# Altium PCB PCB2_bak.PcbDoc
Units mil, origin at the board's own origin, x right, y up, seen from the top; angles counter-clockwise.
Board outline 600 x 1690 mil, 2 copper layers (Top Layer, Bottom Layer), stack 61.756 mil thick; 62 components, 59 nets, 262 pads, 74 vias.
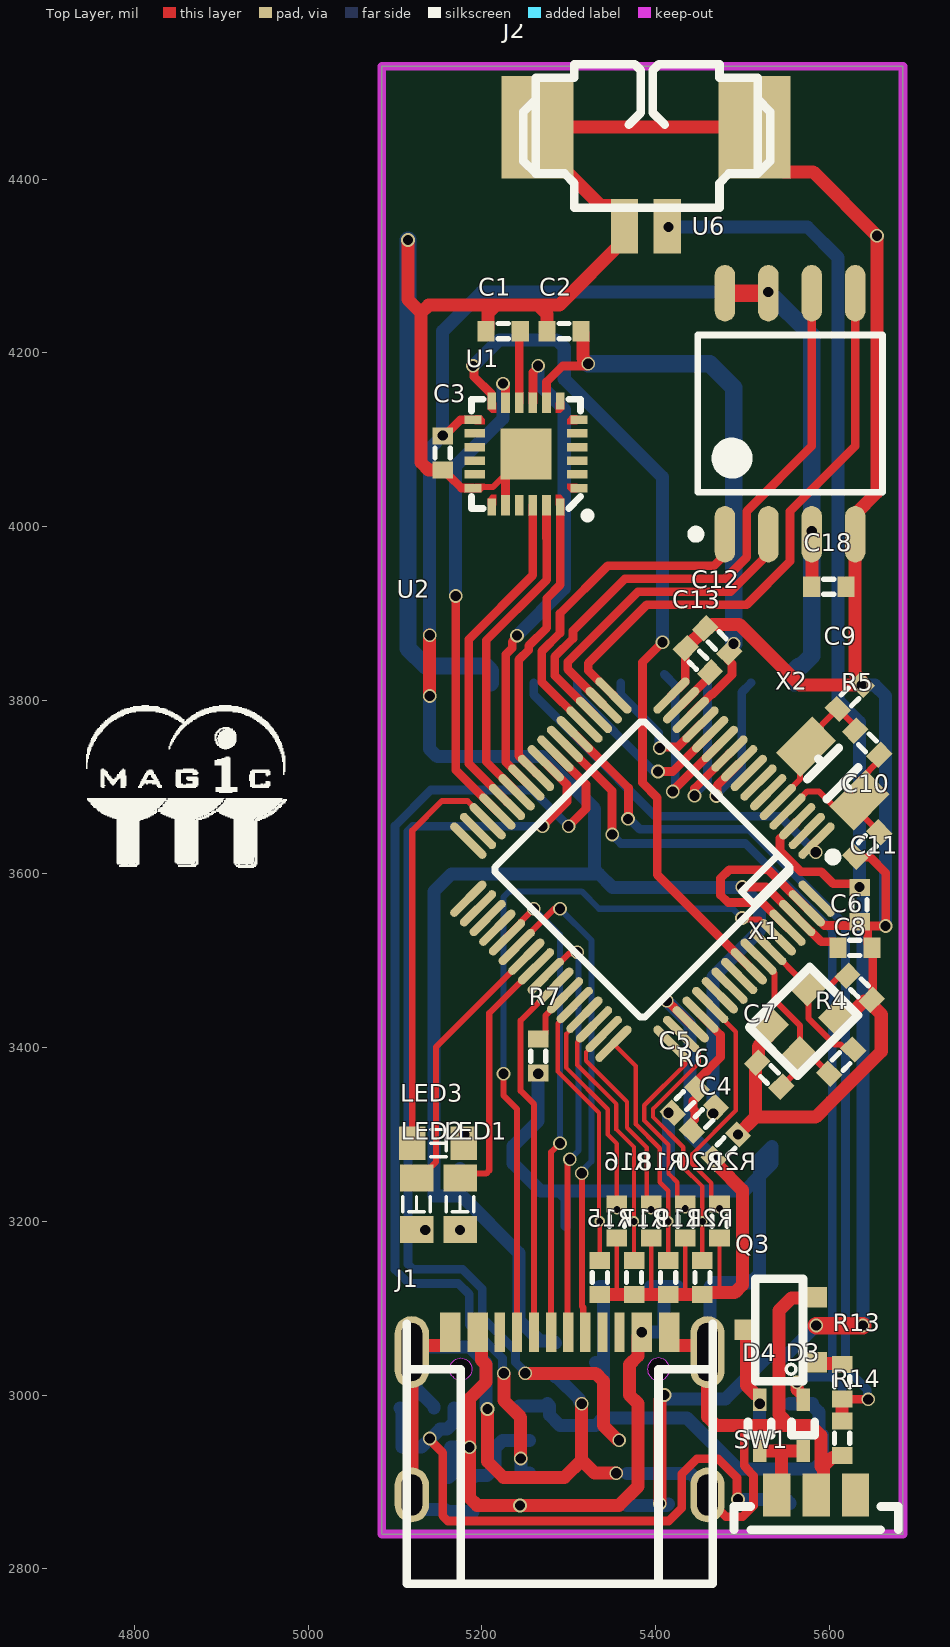
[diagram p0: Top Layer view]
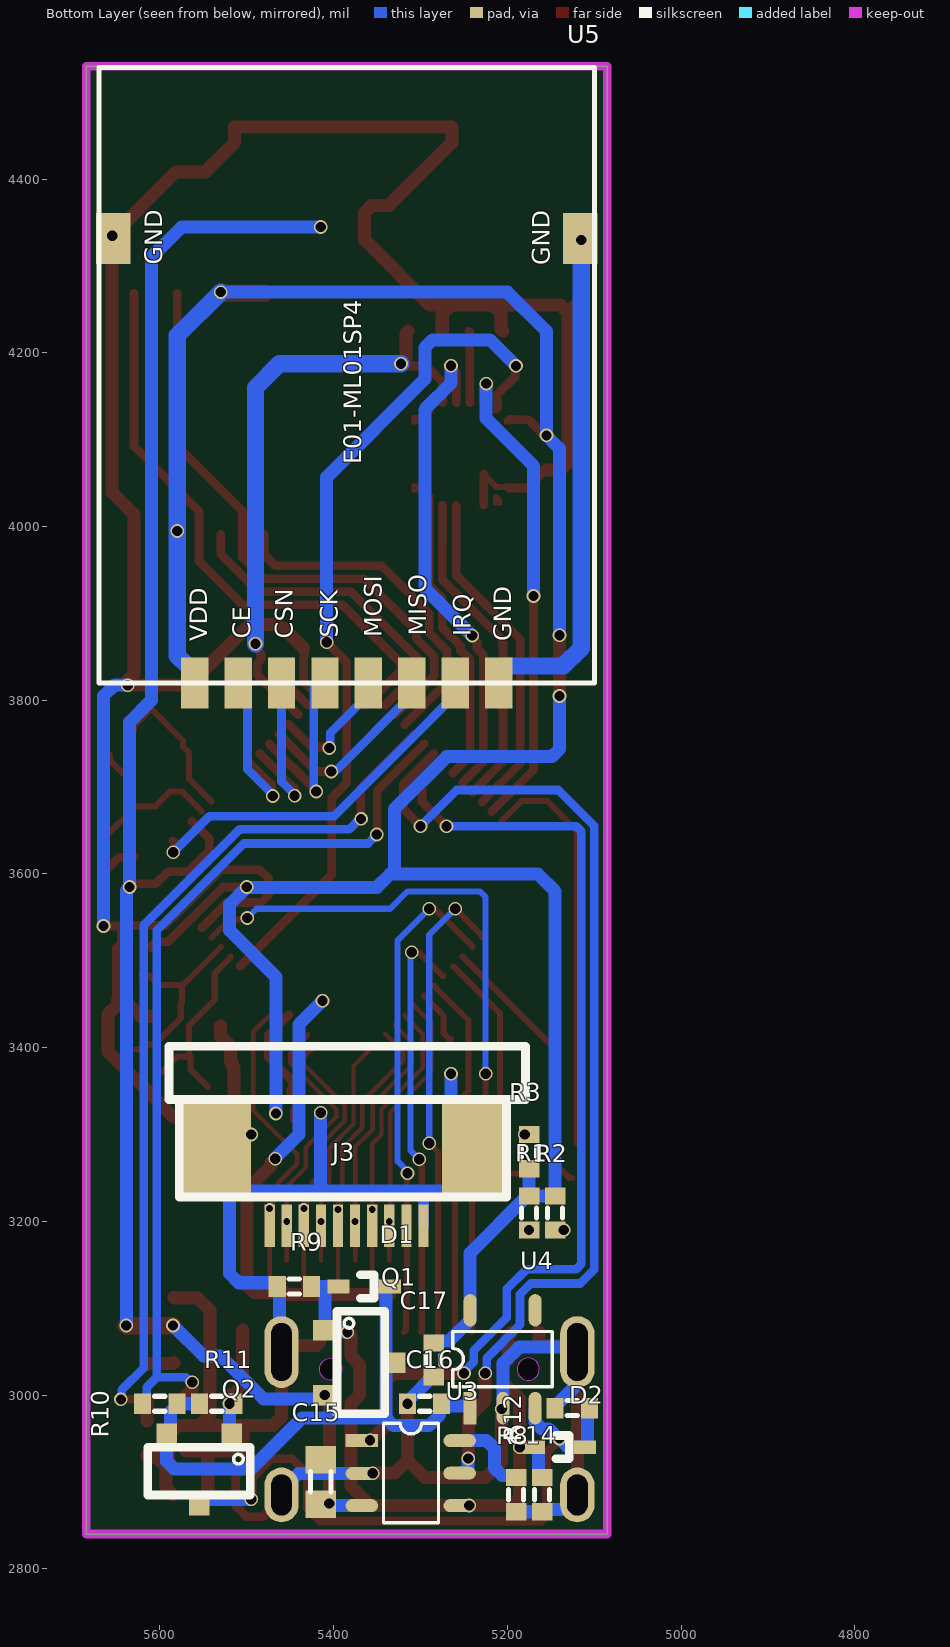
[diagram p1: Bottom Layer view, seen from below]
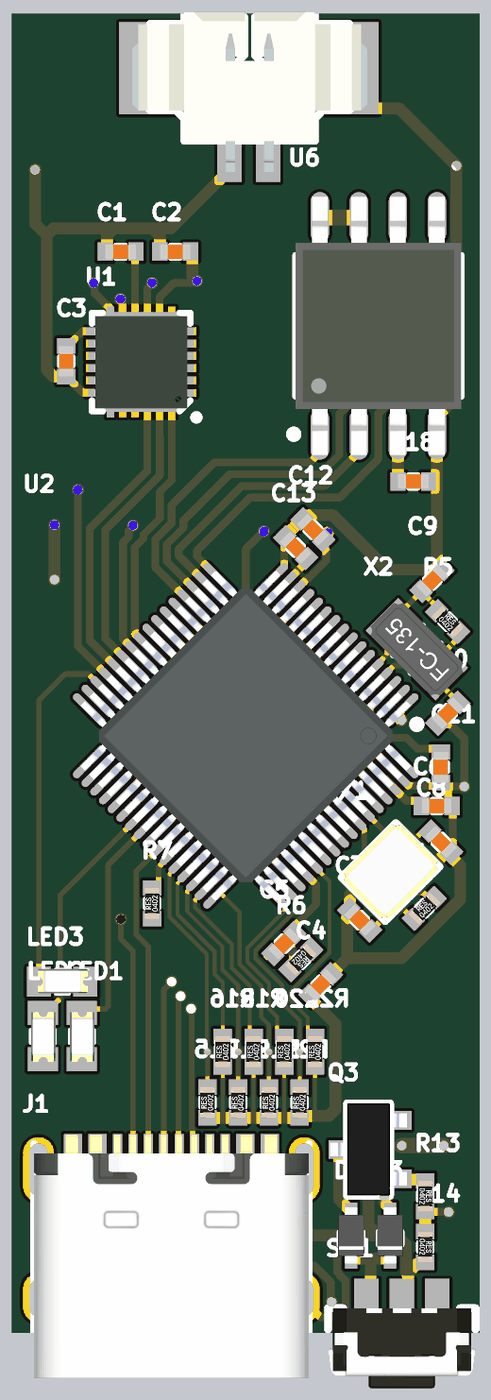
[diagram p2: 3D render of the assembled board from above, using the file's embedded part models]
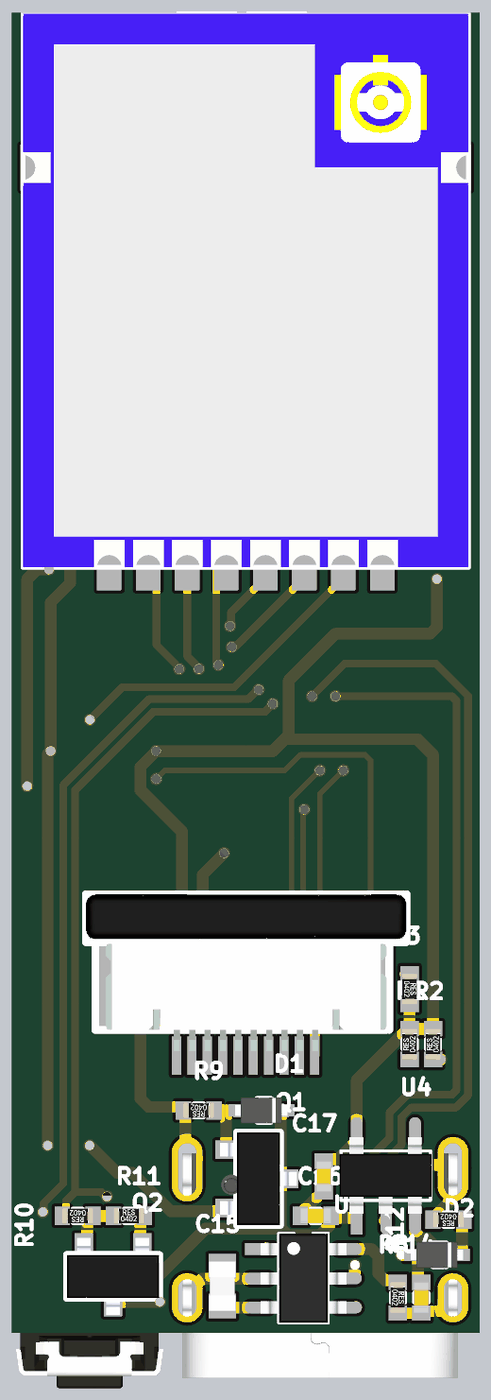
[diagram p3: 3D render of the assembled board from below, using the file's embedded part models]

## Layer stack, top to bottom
Top Solder: solder mask 1, SM-001, Dk 4
Top Layer: signal copper 1.378
Dielectric 1: core 59, Core-043, Dk 4.3
Bottom Layer: signal copper 1.378
Bottom Solder: solder mask 1, SM-001, Dk 4

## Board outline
5085,2840 5085,4530 5685,4530 5685,2840

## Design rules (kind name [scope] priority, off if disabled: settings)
Clearance [All] p1: gap=5 ignorepadtopadclearanceinfootprint=FALSE
PolygonConnect [All] p1: connectstyle=Relief reliefconductorwidth=10 reliefentries=4 polygonreliefangle="90 Angle" airgapwidth=10
RoutingVias [All] p1: holewidth=28 width=50 viastyle="Through Hole" minholewidth=7.87 minwidth=11.81 maxholewidth=28 maxwidth=50
SolderMaskExpansion [All] p1: expansion=4 istentingtop=FALSE
Width [All] p1: maxlimit=40 minlimit=4 preferedwidth=10 minimp=50.000000 maximp=50.000000 favimp=50.000000
30 further rules are at their usual default settings.

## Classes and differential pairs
net class ADC[0..7]: ADC0 ADC1 ADC2 ADC3 ADC4 ADC5 ADC6 ADC7
component class U_W25Q128: C18 U6
component class U_Pressure: J3 R15 R16 R17 R18 R19 R20 R21 R22
component class U_Power: C14 C15 C16 C17 D1 D2 D3 D4 Q1 Q2 Q3 R8 R9 R10 R11 R12 R13 R14 SW1 U3 U4
component class U_NRF24L01_PA_LNA: U5
component class U_NANO103: C4 C5 C6 C7 C8 C9 C10 C11 C12 C13 R4 R5 R6 R7 U2 X1 X2
component class U_ICM_20948: C1 C2 C3 U1
component class Sheet1: J1 J2 LED1 LED2 LED3 R1 R2 R3

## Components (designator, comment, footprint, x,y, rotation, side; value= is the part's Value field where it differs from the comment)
C1 "Cap" CAP_0402 5244.37,4225 r180 top value=0.1uf
C2 "Cap" CAP_0402 5314.37,4225 r180 top value=0.1uf
C3 "Cap" CAP_0402 5155,4104.37 r270 top value=0.1uf
C4 "Cap" CAP_0402 5495,3300 r225 top value=0.1uF
C5 "Cap" CAP_0402 5420,3325 r45 top value=0.1uF
C6 "Cap" CAP_0402 5649.37,3515 r180 top value=0.1uF
C7 "Cap" CAP_0402 5545,3355 r135 top value=22pF
C8 "Cap" CAP_0402 5621.09,3482.84 r315 top value=22pF
C9 "Cap" CAP_0402 5610,3790 r45 top value=22pF
C10 "Cap" CAP_0402 5657.84,3647.84 r225 top value=22pF
C11 "Cap" CAP_0402 5635,3545 r90 top value=0.1uF
C12 "Cap" CAP_0402 5457.16,3882.84 r315 top value=0.1uF
C13 "Cap" CAP_0402 5435,3860 r315 top value=0.1uF
C14 "Cap" CAP_0402 5160,2905 r270 bottom value=1uF
C15 "Cap" Cap_0603 5415,2900 r90 bottom value=10uF
C16 "Cap" CAP_0402 5275.63,2990 r0 bottom value=1uF
C17 "Cap" CAP_0402 5285,3060 r270 bottom value=1uF
C18 "Cap" CAP_0402 5580,3930.71 r0 top value=0.1uF
D1 "B5819WT" SOD-523 5365,3125 r180 bottom
D2 "B5819WT" SOD-523 5140,2940 r180 bottom
D3 "B5819WT" SOD-523 5570,2965 r270 top
D4 "B5819WT" SOD-523 5520,2965 r270 top
J1 "USB TYPE C" USBC-SMD16F 5119.45,2885 r0 top
J2 "Plug2" Terminal_block_2pin_1.25mm_SMD 5390,4460 r0 top
J3 "Plug10" FPC0.5-10PS 5296.57,3195 r0 bottom
LED1 "LED" SMD-0603_LED 5175,3190.55 r90 top
LED2 "LED" SMD-0603_LED 5125,3190.55 r90 top
LED3 "LED" SMD-0603_LED 5179.45,3290 r180 top
Q1 "SI2301DS-T1" SOT-23 5331.26,3037.4 r270 bottom
Q2 "SI2301DS-T1" SOT-23 5555,2875 r0 bottom
Q3 "MMS9013L-TP" SOT-23 5505,3075 r90 top
R1 "Res" RES_0402 5175,3190 r90 bottom value=1K
R2 "Res" RES_0402 5145,3190 r90 bottom value=1K
R3 "Res" RES_0402 5175,3300 r270 bottom value=1K
R4 "Res" RES_0402 5600,3370 r45 top value=1M
R5 "Res" RES_0402 5630,3765 r315 top value=1M
R6 "Res" RES_0402 5469.69,3332.12 r225 top value=0
R7 "Res" RES_0402 5265,3370.63 r90 top value=0
R8 "Res" RES_0402 5190,2905 r270 bottom value=2.2K
R9 "Res" RES_0402 5425.63,3125 r0 bottom value=100K
R10 "Res" RES_0402 5580.63,2990 r0 bottom value=10K
R11 "Res" RES_0402 5554.37,2990 r180 bottom value=100K
R12 "Res" RES_0402 5105.63,2985 r0 bottom value=100K
R13 "Res" RES_0402 5615,3035 r270 top value=2.2K
R14 "Res" RES_0402 5615,2970 r270 top value=10K
R15 "Res" RES_0402 5335.94,3115.63 r90 top value=10K
R16 "Res" RES_0402 5355.63,3180.63 r90 top value=10K
R17 "Res" RES_0402 5375.31,3115.63 r90 top value=10K
R18 "Res" RES_0402 5395,3180.63 r90 top value=10K
R19 "Res" RES_0402 5414.68,3115.63 r90 top value=10K
R20 "Res" RES_0402 5434.37,3180.63 r90 top value=10K
R21 "Res" RES_0402 5454.05,3115.63 r90 top value=10K
R22 "Res" RES_0402 5473.74,3180.63 r90 top value=10K
SW1 "SPST" ST01-111 5630.28,2885 r180 top
U1 "ICM-20948" QFN_24_3X3 5250.94,4083.62 r180 top
U2 "NANO103SD3AE" MCU_LQFP_64_7x7 5385,3605 r225 top
U3 "TP4059" SOT23-6 5342.68,2967.52 r180 bottom
U4 "AP2112K-3.3TRG1" SOT23-5 5262.87,3009.8 r90 bottom
U5 "NRF24L01" NRF24L01P+PA+LNA+IPX 5670.43,4528.66 r180 bottom
U6 "Flash" "8-Pin SOIC 208-mil" 5555,4130 r90 top
X1 "Xtal" 2520S 5610.93,3435.93 r225 top value=12MHz
X2 "Xtal" FC-135 5660.33,3754.32 r135 top value=32.768KHz

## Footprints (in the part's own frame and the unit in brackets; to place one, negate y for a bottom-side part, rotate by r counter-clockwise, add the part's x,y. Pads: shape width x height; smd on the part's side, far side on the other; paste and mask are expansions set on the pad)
"8-Pin SOIC 208-mil" [mm]
  oval 1.65x0.6 smd: 1(-3.525,1.905) 2(-3.525,0.635) 3(-3.525,-0.635) 4(-3.525,-1.905) 5(3.525,-1.905) 6(3.525,-0.635) 7(3.525,0.635) 8(3.525,1.905)
  silkscreen extent -3.65,-2.7 2.3,2.88, body extent -4.2,-2.69 4.2,2.69, height 2.3
2520S [mm]
  rect 0.9x0.8 smd: 1(0,-1.25) 2(1.65,0) ""(0,0) ""(1.65,-1.25)
  silkscreen extent -0.43,-1.63 2.07,0.37, body extent -0.49,-1.69 2.11,0.41, height 0.55
CAP_0402 [mm]
  rect 0.5x0.6 smd: 1(0,0) 2(1,0)
  silkscreen extent 0.35,-0.22 0.65,0.22, body extent 0,-0.25 1,0.25, height 0.48
Cap_0603 [mm]
  rect 0.8x0.9 smd: 1(-0.65,0) 2(0.65,0)
  silkscreen extent -0.3,-0.3 0.3,0.3, body extent -0.8,-0.43 0.8,0.43, height 0.83
FC-135 [mm]
  rect 1x1.5 smd: 1(-0.79,1.7) 2(1.42,1.7)
  silkscreen extent -0.29,1.05 0.92,2.35, body extent -1.28,0.95 1.92,2.45, height 0.8
FPC0.5-10PS [mm]
  rect 0.3x1.25 smd: 1(0,0) 2(0.5,0) 3(1,0) 4(1.5,0) 5(2,0) 6(2.5,0) 7(3,0) 8(3.5,0) 9(4,0) 10(4.5,0)
  rect 2x3 smd: ""(-1.54,-2.325) ""(6.04,-2.32)
  silkscreen extent -2.99,-5.25 7.44,-0.84, body extent -2.99,-5.25 7.44,-0.14, height 2.03
MCU_LQFP_64_7x7 [mm]
  oval 1.4x0.25 smd: 1(-4.2,3) 2(-4.2,2.6) 3(-4.2,2.2) 4(-4.2,1.8) 5(-4.2,1.4) 6(-4.2,1) 7(-4.2,0.6) 8(-4.2,0.2) 9(-4.2,-0.2) 10(-4.2,-0.6) 11(-4.2,-1) 12(-4.2,-1.4) 13(-4.2,-1.8) 14(-4.2,-2.2) 15(-4.2,-2.6) 16(-4.2,-3) 33(4.2,-3) 34(4.2,-2.6) 35(4.2,-2.2) 36(4.2,-1.8) 37(4.2,-1.4) 38(4.2,-1) 39(4.2,-0.6) 40(4.2,-0.2) 41(4.2,0.2) 42(4.2,0.6) 43(4.2,1) 44(4.2,1.4) 45(4.2,1.8) 46(4.2,2.2) 47(4.2,2.6) 48(4.2,3)
  oval 0.25x1.4 smd: 17(-3,-4.2) 18(-2.6,-4.2) 19(-2.2,-4.2) 20(-1.8,-4.2) 21(-1.4,-4.2) 22(-1,-4.2) 23(-0.6,-4.2) 24(-0.2,-4.2) 25(0.2,-4.2) 26(0.6,-4.2) 27(1,-4.2) 28(1.4,-4.2) 29(1.8,-4.2) 30(2.2,-4.2) 31(2.6,-4.2) 32(3,-4.2) 49(3,4.2) 50(2.6,4.2) 51(2.2,4.2) 52(1.8,4.2) 53(1.4,4.2) 54(1,4.2) 55(0.6,4.2) 56(0.2,4.2) 57(-0.2,4.2) 58(-0.6,4.2) 59(-1,4.2) 60(-1.4,4.2) 61(-1.8,4.2) 62(-2.2,4.2) 63(-2.6,4.2) 64(-3,4.2)
  silkscreen extent -4.32,-3.1 3.1,3.8, body extent -4.5,-4.5 4.5,4.5, height 1.55
NRF24L01P+PA+LNA+IPX [mm]
  rect 0.8x1.5 smd: 1(2.805,-18) 2(4.075,-18) 3(5.345,-18) 4(6.615,-18) 5(7.885,-18) 6(9.155,-18) 7(10.425,-18) 8(11.695,-18)
  rect 1x1.5 smd: 9(14.08,-5) 10(0.42,-5)
  silkscreen extent 0,-18 14.5,0, body extent 0,-18 14.5,0, height 2.6
QFN_24_3X3 [mm]
  rect 0.495x0.25 smd paste-1: 1(-1.552,1) 6(-1.552,-1) 18(1.552,1)
  rect 0.6x0.25 smd paste-1: 2(-1.5,0.6) 3(-1.5,0.2) 4(-1.5,-0.2) 5(-1.5,-0.6) 14(1.5,-0.6) 15(1.5,-0.2) 16(1.5,0.2) 17(1.5,0.6)
  rect 0.25x0.495 smd paste-1: 7(-1,-1.552) 24(-1,1.552)
  rect 0.25x0.6 smd paste-1: 8(-0.6,-1.5) 9(-0.2,-1.5) 10(0.2,-1.5) 11(0.6,-1.5) 20(0.6,1.5) 21(0.2,1.5) 22(-0.2,1.5) 23(-0.6,1.5)
  rect 0.25x0.495 smd: 12(1,-1.552) 19(1,1.552)
  rect 0.495x0.25 smd: 13(1.552,-1)
  rect 1.49x1.49 smd: 25(0,0)
  Top Layer region: 1.125,-1.305 1.125,-1.5 0.875,-1.5 0.875,-1.2 1.02,-1.2
  Top Layer region: -0.875,1.2 -1.02,1.2 -1.125,1.305 -1.125,1.5 -0.875,1.5
  Top Layer region: 1.125,1.305 1.02,1.2 0.875,1.2 0.875,1.5 1.125,1.5
  Top Layer region: 1.5,0.875 1.2,0.875 1.2,1.02 1.305,1.125 1.5,1.125
  Top Layer region: 1.5,-1.125 1.305,-1.125 1.2,-1.02 1.2,-0.875 1.5,-0.875
  Top Layer region: -1.2,-1.02 -1.305,-1.125 -1.5,-1.125 -1.5,-0.875 -1.2,-0.875
  Top Layer region: -0.875,-1.5 -1.125,-1.5 -1.125,-1.305 -1.02,-1.2 -0.875,-1.2
  Top Layer region: -1.2,1.02 -1.2,0.875 -1.5,0.875 -1.5,1.125 -1.305,1.125
  silkscreen extent -1.87,-1.6 1.6,1.87, body extent -1.51,-1.5 1.5,1.51, height 0.98
RES_0402 [mm]
  rect 0.5x0.6 smd: 1(0,0) 2(1,0)
  silkscreen extent 0.35,-0.22 0.65,0.22, body extent 0,-0.25 1,0.25, height 0.35
SMD-0603_LED [mm]
  rect 0.78x0.98 smd: 1(0,0) 2(1.51,0)
  silkscreen extent 0.52,-0.4 0.97,0.4, body extent -0.08,-0.41 1.54,0.45, height 0.6
SOD-523 [mm] "SODFL, 2-Leads, Body 0.80x1.60mm, IPC Medium Density"
  rect 0.65x0.4 smd: 1(-0.75,0) 2(0.75,0)
  silkscreen extent -0.11,-0.34 0.29,0.34, body extent -0.92,-0.42 0.91,0.42, height 0.71
SOT23-5 [mm]
  rect 0.95x0.38 smd: 1(-0.63,-0.51)
  oval 0.95x0.38 smd: 2(-0.63,-1.47) 3(-0.63,-2.41) 4(2.23,-2.41) 5(2.23,-0.51)
  silkscreen extent 0,-2.91 1.61,0, body extent -0.44,-2.95 2.06,0.05, height 1.09
SOT23-6 [mm]
  rect 0.95x0.38 smd: 1(-0.63,-0.51)
  oval 0.95x0.38 smd: 2(-0.63,-1.47) 3(-0.63,-2.41) 4(2.23,-2.41) 5(2.227,-1.461) 6(2.23,-0.51)
  silkscreen extent 0,-2.91 1.61,0, body extent -0.59,-2.91 2.21,-0.01, height 1.45
SOT-23 [mm]
  rect 0.6x0.7 smd: 1(-0.95,-2) 2(0.95,-2) 3(0,0)
  silkscreen extent -1.5,-1.65 1.5,-0.25, body extent -1.5,-2.2 1.5,0.3, height 1.05
ST01-111 [mm]
  rect 0.8x1.25 smd: 1(0,0) 1(2.3,0) 2(1.15,0)
  silkscreen extent -1.25,0.34 3.55,1.02, body extent -1.25,0.34 3.55,2.94, height 1.05
Terminal_block_2pin_1.25mm_SMD [mm]
  rect 0.8x1.6 smd: 1(-0.65,-2.9) 2(0.6,-2.9)
  rect 2.1x3 smd: ""(-3.2,0) ""(3.15,0)
  silkscreen extent -3.61,-2.36 3.61,1.84, body extent -3.83,-3.37 3.82,1.83, height 3.4
USBC-SMD16F [mm]
  rect 0.6x1.15 smd: 1(1.125,4.76) 2(1.925,4.76) 11(6.725,4.76) 12(7.525,4.76)
  rect 0.3x1.15 smd: 3(2.575,4.76) 4(3.075,4.76) 5(3.575,4.76) 6(4.075,4.76) 7(4.575,4.76) 8(5.075,4.76) 9(5.575,4.76) 10(6.075,4.76)
  oval 1x1.6 hole 0.6 slot 1.2 at 90 deg: ""(0,0) ""(8.65,0)
  oval 1x2.1 hole 0.6 slot 1.7 at 90 deg: ""(0,4.18) ""(8.65,4.18)
  Keep-Out Layer board cut-out: 6.89,3.68 6.915,3.556 6.985,3.45 7.091,3.38 7.215,3.355 7.215,3.355 7.339,3.38 7.445,3.45 7.515,3.556 7.54,3.68 7.54,3.68 7.515,3.804 7.445,3.91 7.339,3.98 7.215,4.005 7.215,4.005 7.091,3.98 6.985,3.91 6.915,3.804 6.89,3.68
  Keep-Out Layer board cut-out: 1.435,3.355 1.311,3.38 1.205,3.45 1.135,3.556 1.11,3.68 1.11,3.68 1.135,3.804 1.205,3.91 1.311,3.98 1.435,4.005 1.435,4.005 1.559,3.98 1.665,3.91 1.735,3.804 1.76,3.68 1.76,3.68 1.735,3.556 1.665,3.45 1.559,3.38 1.435,3.355
  Keep-Out Layer pour cut-out: 1.31,3.87
  silkscreen extent -0.15,-2.6 8.8,5, body extent -0.15,-2.6 8.8,5.3, height 3.16

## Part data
D1 D2 D3 D4: "Diode Schottky 40V 1A 2-Pin SOD-523 T/R", Average Rectified Current=1A, Forward Voltage=550mV, Manufacturer=MCC, Manufacturer Part Number=B5819W-TP, Max Forward Surge Current (Ifsm)=10A, Max Operating Temperature=125°C, Max Power Dissipation=250mW, Max Repetitive Reverse Voltage (Vrrm)=40V, Max Reverse Voltage (DC)=20V, Min Operating Temperature=-65°C, Package Quantity=3000, Peak Reverse Current=1mA
J1: "USB Shielded I/O Receptacle; Type C; Right Angle; Surface Mount; Gold over Nickel", Case/Package=0101, Current Rating=5A, Flammability Rating="UL94 V-0", Insulation Color=Black, Manufacturer=Molex, Manufacturer Part Number=105450-0101, Max Operating Temperature=85°C, Min Operating Temperature=-30°C, Supplier Part Number 1=WM12856DKR-ND
Q1 Q2: "Trans MOSFET P-CH 20V 2.3A 3-Pin TO-236 T/R", Case/Package=SOT-23-3, Continuous Drain Current (ID)=2.3A, Drain to Source Resistance=130mR, Drain to Source Voltage (Vdss)=-20V, Gate to Source Voltage (Vgs)=8V, Manufacturer="Vishay Siliconix", Max Operating Temperature=150°C, Max Power Dissipation=1.25W, Min Operating Temperature=-55°C, Package Quantity=3000
Q3: "Trans GP BJT NPN 25V 0.5A 3-Pin SOT-23 T/R", Case/Package=SOT-23, Collector Base Voltage (VCBO)=40V, Collector Emitter Voltage (VCEO)=25V, Emitter Base Voltage (VEBO)=5V, Frequency=150MHz, Manufacturer=MCC, Max Operating Temperature=150°C, Min Operating Temperature=-55°C, Power Dissipation=300mW, Supplier Part Number 1=MMS9013-L-TP
SW1: library part Switch_Button1
U1: "Accelerometer, Gyroscope, Magnetometer, 9 Axis Sensor IÂ²C, SPI Output", Package="QFN-24 InvenSense"
U3: "600MA SOT23-6"
U4: "IC REG LINEAR 3.3V 600MA SOT23-5", Case/Package=SOT-23-5, Dropout Voltage=250mV, Manufacturer=Diodes, Max Input Voltage=6V, Max Operating Temperature=85°C, Max Output Current=600mA, Min Input Voltage=2.5V, Min Operating Temperature=-40°C, Output Voltage=3.3V, Package Quantity=1, Quiescent Current=55uA, Supplier Part Number 1=AP2112K-3.3TRG1DICT-ND
U5: library part NRF24L01_module
U6: library part W25QXX

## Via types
v1: diameter 15.75, hole 11.81, Top Layer to Bottom Layer, tented both sides, 66 vias
v2: diameter 11.81, hole 7.87, Top Layer to Bottom Layer, tented both sides, 8 vias

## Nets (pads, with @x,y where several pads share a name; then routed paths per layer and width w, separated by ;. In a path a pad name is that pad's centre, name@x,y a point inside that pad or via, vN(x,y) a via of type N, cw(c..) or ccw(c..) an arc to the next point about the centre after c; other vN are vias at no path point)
12M_I: C7.1 R4.1 U2.58 X1.2 | length 221.7
  Top Layer w7: U2.58 5518.63,3504.01 5536.92,3485.72 5536.92,3455.16 5566.39,3425.68 5566.39,3391.39 X1.2 ; C7.1 5565,3375 X1.2 ; R4.1 5580,3390 X1.2
12M_O: C8.1 R4.2 U2.59 X1.1 | length 219.8
  Top Layer w7: U2.59 5574.94,3470.73 X1.1 ; C8.1 5612.12,3482.84 5601.41,3472.12 5577.53,3472.12 X1.1 ; R4.2 5618.87,3397.84 5612.94,3403.77 5606.02,3403.77 5576.14,3433.66 5576.14,3450.63 5574.74,3452.02 5574.74,3469.34 X1.1
/RESET: J1.4 U2.60 | length 847.8
  Top Layer w7: v1(5225,3370) 5225,3345 5240.51,3329.49 J1.4 ; v1(5499.63,3549.25) 5500,3549.25 5501.67,3547.58 5519.6,3547.58 5540.13,3527.05 U2.60
  Bottom Layer w7: v1(5225,3370) 5225,3573.16 5231.84,3580 5315,3580 5335,3560 5488.88,3560 v1(5499.63,3549.25)
ADC0: J3.3 R15.2 U2.44 | length 322.3
  Top Layer w5: U2.44 5307.05,3447.79 5287.42,3428.16 5287.42,3372.58 5335,3325 5335,3200.95 v2(5335.94,3200) R15.2
ADC1: J3.4 R16.2 U2.45 | length 250.7
  Top Layer w5: U2.45 5318.19,3436.66 5297.42,3415.89 5297.42,3376.73 5345,3329.14 5345,3300 5355.63,3289.37 R16.2
  other v2: 5355.63,3213.7
ADC2: J3.5 R17.2 U2.46 | length 306.9
  Top Layer w5: U2.46 5329.32,3425.52 5310,3406.2 5310,3380 5355,3335 5355,3305.86 5375.31,3285.54 v2(5375.31,3200) R17.2
ADC3: J3.6 R18.2 U2.47 | length 235.2
  Top Layer w5: U2.47 5340.46,3415.46 5320,3395 5320,3385 5326.71,3378.29 5367.19,3337.81 5367.19,3307.81 5390,3285 5390,3225 R18.2
  other v2: 5395,3213.7
ADC4: J3.7 R19.2 U2.48 | length 275.7
  Top Layer w5: U2.48 5377.19,3378.96 5377.19,3311.95 5405,3284.14 5405,3245 5414.69,3235.32 v2(5414.69,3200) R19.2
ADC5: J3.8 R20.2 U2.49 | length 231.3
  Top Layer w5: U2.49 5434.27,3388.69 5434.27,3380.73 5387.19,3333.64 5387.19,3316.1 5415,3288.28 5415,3255 5425.06,3244.94 5425.06,3227.34 5432.4,3220 R20.2
  other v2: 5434.37,3215
ADC6: J3.9 R21.2 U2.50 | length 314.6
  Top Layer w5: U2.50 5429.54,3414.39 5450,3393.93 5450,3382.31 5397.19,3329.5 5397.19,3320.24 5432.01,3285.42 5432.01,3262.13 5454.06,3240.09 v2(5454.06,3200) R21.2
ADC7: J3.10 R22.2 U2.53 | length 276.6
  Top Layer w5: U2.53 5462.95,3447.79 5492.5,3418.24 5492.5,3327.62 5442.01,3277.13 5442.01,3266.28 5464.43,3243.86 5464.43,3227.34 5471.77,3220 R22.2
  other v2: 5473.74,3215
AVDD: C5.2 R6.2 U2.52 | length 161.9
  Top Layer w10: R6.2 5440.46,3305.68 5440.46,3312.52 5445.31,3317.38 5445.31,3327.75 5443.17,3329.89 5443.17,3338.54 5449.23,3344.6 5449.23,3351.45 C5.2 5446.81,3353.86 5446.81,3360.71 5475,3388.9 5475,3414.67 5451.81,3437.86 U2.52
AVSS: R7.2 U2.43 | length 64.2
  Top Layer w7: R7.2 5266.97,3410 5273.31,3416.34 5273.31,3436.86 5295.92,3459.47 U2.43
CE: U2.9 U5.2 | length 195.1
  Top Layer w10: v1(5470.14,3689.86) 5471.24,3690.96 5471.24,3702.26 5496.36,3727.38 U2.9
  Bottom Layer w10: v1(5470.14,3689.86) 5470.14,3691.42 5499.25,3720.53 5499.25,3809.25 U5.2
ICE_CLK: J1.5 U2.42 | length 422
  Top Layer w7: J1.5 5260.2,3334.8 5244.69,3350.31 5244.69,3431.28 U2.42
ICE_DAT: J1.7 U2.41 | length 491.6
  Top Layer w7: U2.41 5274.41,3482.51 5300.23,3508.33 5308.33,3508.33 v1(5310,3510) ; J1.7 5298.63,3073.34 5298.63,3268.63 v1(5301.47,3271.47)
  Bottom Layer w7: v1(5301.47,3271.47) 5311.37,3281.37 5311.37,3508.63 v1(5310,3510)
INT: U2.1 U5.7 | length 432.4
  Top Layer w10: v1(5584.63,3625) 5578.39,3631.24 5578.39,3631.35 U2.1
  Bottom Layer w10: U5.7 5260,3806.22 5313.72,3752.5 5399.72,3666.5 5543.13,3666.5 v1(5584.63,3625)
INT1: U1.12 U2.57 | length 990
  Top Layer w10: v1(5190,4185) 5191.1,4183.9 5191.1,4172.68 5211.5,4152.28 5211.5,4144.82 U1.12 ; v1(5408.11,3866.89) 5385,3843.79 5385,3705 5402.13,3687.87 5402.13,3599.01 U2.57
  Bottom Layer w15: v1(5190,4185) 5220,4215 5286.21,4215 5295,4206.21 5295,4170 5408.11,4056.89 v1(5408.11,3866.89)
LDO: C2.1 C12.2 U1.8 U2.14 | length 689.9
  Top Layer w10: U1.8 5274.65,4142.76 5274.65,4166.56 5293.09,4185 5320,4185 v1(5322.55,4187.55) ; U2.14 5440.79,3783.17 5464.47,3806.85 5465.59,3806.85 5488.15,3829.41 5488.15,3842.22 5483.61,3846.76 5483.61,3853.61 C12.2
  Top Layer w15: C2.1 5316.71,4222.66 5316.71,4193.59 5322.55,4187.75 v1(5322.55,4187.55)
  Bottom Layer w20: v1(5322.55,4187.55) 5462.45,4187.55 5490,4160 v1(5490,3865)
NetC1_1: C1.1 U1.10 | length 82.9
  Top Layer w10: U1.10 5243.15,4142.76 5243.15,4223.78 C1.1
NetC13_2: C13.2 U2.15 | length 51.6
  Top Layer w10: U2.15 5429.54,3794.42 5462.84,3827.71 C13.2
NetC14_1: C14.1 D1.1 D2.1 J1.2 J1.11 Q1.1 R9.1 U3.4 | length 748.1
  Top Layer w15: J1.2 5199.55,3068.09 5199.55,3040.45 5205,3035 5205,3015 5185.99,2995.99 5185.99,2940.07 v1(5185.85,2939.93) 5185.85,2881.8 5194.63,2873.02 5243.79,2873.02 v1(5243.93,2872.87) 5357.87,2872.87 5380,2895 5380,2990 5370,3000 5370,3035 5379.9,3044.9 5379.9,3068.09 v1(5384.21,3072.4)
  Bottom Layer w15: C14.1 5161.97,2905 5164.31,2907.34 5164.31,2939.63 5164.69,2940 D2.1 ; v1(5384.21,3072.4) 5384.36,3072.54 5407.74,3072.54 Q1.1 5410.08,3074.88 5410.08,3125 ; D1.1 5410.08,3125 ; R9.1 5410.08,3125
NetC16_1: C16.1 D1.2 Q1.3 Q2.2 R10.1 R11.1 U4.1 | length 667.8
  Bottom Layer w15: U4.1 5242.8,2987.48 5273.29,2987.5 5275.63,2989.84 C16.1 5277.97,2987.66 5277.97,2977.03 5290,2965 5331.21,2965 5340,2973.79 ; Q1.3 5333.23,3037.4 5337.54,3033.09 5337.54,3031.12 Q1.3@5340,3028.66 ; D1.2 5339.63,3125 5340,3124.63 Q1.3@5340,3028.66 ; R11.1 R10.1 5580.63,2988.03 5588.09,2980.57 5588.09,2958.05 Q2.2 5592.4,2923.79 5583.61,2915 5495,2915 5436.21,2973.79 5340,2973.79 ; 5340,2973.79 Q1.3@5340,3028.66
NetD2_2: D2.2 Q2.3 R12.1 U4.3 | length 719.9
  Top Layer w10: v1(5140,2950) 5140,2948.44 5155,2933.44 5155,2860.86 5160.86,2855 5415.31,2855 5430.31,2870 5430.31,2909.11 5447.7,2926.5 5472.3,2926.5 5493.9,2904.89 5493.9,2881.1 v1(5495,2880)
  Bottom Layer w15: R12.1 5107.97,2982.66 5107.97,2940.37 5108.35,2940 D2.2 5110.85,2940.37 5130.84,2940.37 5139.86,2949.39 5139.86,2949.65 5139.96,2949.76 v1@5140.24,2949.76 ; v1@5140.59,2949.41 5151.87,2960.69 5160.02,2960.69 5167.97,2968.64 U4.3 ; v1(5495,2880) 5550.69,2880 5555,2875.69 Q2.3
NetD3_2: D3.2 D4.2 SW1.1@5539.72,2885 | length 102.7
  Top Layer w15: D4.2 5545,2935.47 ; SW1.1@5539.72,2885 5545,2890.28 5545,2935.47 ; D3.2 5545,2935.47
NetD4_1: D4.1 Q2.1 Q3.3 R11.2 | length 129.8
  Top Layer w15: 5505,3010.9 5516.08,2999.82 5519.63,2999.82 5520,2999.45 D4.1 v1(5520,2990) ; 5505,3011.63 Q3.3
  Bottom Layer w15: Q2.1 5520,2956.14 v1(5520,2990)
NetLED1_1: LED1.1 R1.1
  other v1: 5175,3190
NetLED2_1: LED2.1 R2.1
  other v1: 5135,3190
NetLED3_1: LED3.1 R3.1
  other v1: 5180,3300
NetQ3_2: Q3.1 R13.1 | length 32.3
  Top Layer w15: Q3.1 5585.04,3036.3 5613.7,3036.3 R13.1
NetR8_1: R8.1 U3.6 | length 95.7
  Bottom Layer w15: R8.1 5192.34,2907.34 5206.21,2907.34 5215,2916.13 5215,2938.65 5223.79,2947.44 U3.6
PA12_PWM0: LED1.2 U2.40 | length 294.5
  Top Layer w7: LED1.2 5180,3255 5205,3255 5208.63,3258.63 5208.63,3439.76 U2.40
PA13_PWM1: LED2.2 U2.39 | length 309.4
  Top Layer w7: LED2.2 5128.94,3250 5147.21,3268.27 5147.21,3400.62 U2.39
PB11_PWM4: LED3.2 U2.30 | length 470.6
  Top Layer w7: LED3.2 5120,3650 5154,3684 5183.56,3684 U2.30 U2.30
PD6: R13.2 R14.1 U2.21 | length 1037.1
  Top Layer w10: U2.21 5368.9,3699.05 5368.9,3666.1 5368.42,3665.62 v1(5368.42,3663.42) ; R13.2 5615.31,2995.32 5644.69,2995.32 v1(5645,2995)
  Top Layer w15: R14.1 R13.2
  Bottom Layer w10: v1(5368.42,3663.42) 5369.98,3663.42 5381.9,3651.5 5508.27,3651.5 5575,3584.78 ; 5575,3584.77 5618.74,3541.03 5618.74,3031.26 5643.9,3006.1 5643.9,2996.1 v1(5645,2995)
PD7: D3.1 R10.2 U2.22 | length 1044.3
  Top Layer w10: U2.22 5350,3695.68 5350,3645.75 v1(5350.37,3645.37)
  Top Layer w15: v1(5562.86,3014.68) 5563,3014.54 5563,3006.45 5570,2999.45 D3.1
  Bottom Layer w10: v1(5350.37,3645.37) 5350.37,3645 5360.37,3635 5503.56,3635 5560,3578.56 5603.74,3534.82 5603.74,3026.26 5603.74,3020.54 ; v1(5562.86,3014.68) 5564.41,3014.68 5570.27,3020.54 5603.74,3020.54 ; R10.2 5615.16,2994.84 5615.16,3009.13 5603.74,3020.54
PD14: U2.23 U3.5 | length 1189.5
  Top Layer w10: U2.23 5320,3703.41 5320,3675 v1(5300,3655)
  Top Layer w15: v1(5225.37,3025) 5225.52,3024.86 5225.52,2993.77 5244.86,2974.43 5244.86,2927.19 v1(5245,2927.05)
  Bottom Layer w10: v1(5225.37,3025) 5223.9,3026.47 5223.9,3042.45 5185.47,3080.88 5185.47,3116.06 5173.07,3128.46 5116.19,3128.46 5100,3144.64 5100,3655.36 5141.35,3696.7 5258.3,3696.7 v1(5300,3655)
  Bottom Layer w15: v1(5245,2927.05) 5245.14,2926.9 5245.14,2910.02 U3.5
PD15: U2.24 U3.1 | length 1135.2
  Top Layer w10: v1(5270,3655) 5298.2,3683.2 5298.2,3702.82 5273.64,3727.38 U2.24
  Top Layer w15: v1(5250,3025) 5331.21,3025 5340,3016.21 5340,2965 5356.78,2948.22 5358.02,2948.22 v1(5358.16,2948.08)
  Bottom Layer w10: v1(5250,3025) 5250,3026.56 5238.9,3037.66 5238.9,3051.1 5200.72,3089.28 5200.72,3122.02 5177.74,3145 5120.86,3145 5115,3150.86 5115,3649.14 5120.86,3655 v1(5270,3655)
PE5: U1.11 U2.29 | length 558.4
  Top Layer w10: v1(5170,3920) 5170,3719.78 U2.29 ; v1(5224.43,4164.63) 5224.43,4163.07 5227.24,4160.26 5227.24,4142.76 U1.11
  Bottom Layer w15: v1(5170,3920) 5170,4070 5224.43,4124.43 v1(5224.43,4164.63)
RX0: J1.8 U2.38 | length 577.6
  Top Layer w7: U2.38 5240.24,3516.68 5283.55,3560 v1(5290,3560) ; v1(5315,3255.37) 5315,3250 5315.63,3249.37 5315.63,3102.27 5316.85,3101.05 5316.85,3074.81 J1.8
  Bottom Layer w7: v1(5290,3560) 5326.37,3523.63 5326.37,3269.12 5315,3257.74 v1(5315,3255.37)
SPI0_MISO: U1.9 U2.26 | length 575
  Top Layer w10: v1(5240.54,3874.46) 5240.54,3872.9 5234.94,3867.3 5234.94,3859.94 5227.72,3852.72 5227.72,3728.99 5251.37,3705.33 U2.26 ; U1.9 5258.9,4142.76 5258.9,4177.62 5264.86,4183.58 v1(5264.86,4185.14)
  Bottom Layer w15: v1(5240.54,3874.46) 5295,3928.92 5295,4135 5264.86,4165.14 v1(5264.86,4185.14)
SPI0_MOSI: U1.24 U2.25 | length 334.1
  Top Layer w10: U2.25 5262.51,3716.47 5242.72,3736.26 5242.72,3846.5 5254.08,3857.87 5254.08,3862.72 5275,3883.64 5275,3917.57 5290.31,3932.89 U1.24
SPI0_SCLK: U1.23 U2.27 | length 374.3
  Top Layer w10: U2.27 5240.24,3694.2 5205,3729.43 5205,3868.79 5275,3938.79 5275,3986.2 5274.65,3986.55 5274.65,4024.49 U1.23
SPI0_SS: U1.22 U2.28 | length 390.5
  Top Layer w10: U2.28 5229.1,3683.06 5185,3727.16 5185,3870 5258.82,3943.82 U1.22
SPI1_MISO: U2.18 U6.2 | length 372.1
  Top Layer w10: U2.18 5340.46,3794.42 5299.08,3835.79 5299.08,3844.08 5380,3925 5383.79,3925 5486.51,3925 5530,3968.49 U6.2
SPI1_MOSI: U2.17 U6.5 | length 670
  Top Layer w10: U2.17 5322.66,3834.37 5322.66,3842.66 5390,3910 5505,3910 5555,3960 5555,4017.74 5630,4092.74 U6.5
SPI1_SCLK: U2.19 U6.6 | length 694.5
  Top Layer w10: U2.19 5284.08,3828.41 5284.08,3850.29 5305,3871.21 5305,3880 5365,3940 5377.57,3940 5480.29,3940 5505,3964.71 5505,4017.74 5580,4092.74 U6.6
SPI1_SS: U2.20 U6.1 | length 398.6
  Top Layer w10: U2.20 5269.08,3821.14 5269.08,3856.51 5290,3877.43 5290,3900 5345,3955 5467.33,3955 5480,3967.67 U6.1
SPI2_MISO: U2.12 U5.6 | length 221
  Top Layer w10: v1(5402.87,3718.09) 5420.03,3718.09 5462.84,3760.9 U2.12
  Bottom Layer w10: U5.6 5310,3806.22 5397.04,3719.19 5401.03,3719.19 5402.13,3718.09 v1(5402.87,3718.09)
SPI2_MOSI: U2.13 U5.5 | length 151.7
  Top Layer w10: v1(5405,3745) 5406.1,3746.1 5425.77,3746.1 5451.7,3772.03 U2.13
  Bottom Layer w10: U5.5 5360,3806.22 5403.9,3762.32 5403.9,3746.1 v1(5405,3745)
SPI2_SCLK: U2.11 U5.4 | length 218.7
  Top Layer w10: v1(5420,3695) 5420,3695.68 U2.11
  Bottom Layer w10: U5.4@5410,3830 5422.87,3817.13 5422.87,3697.87 v1(5420,3695)
SPI2_SS: U2.10 U5.3 | length 201.5
  Top Layer w10: v1(5445,3690) 5445,3698.41 U2.10
  Bottom Layer w10: v1(5445,3690) 5445,3691.56 5460,3706.56 U5.3
TX0: J1.6 U2.37 | length 550
  Top Layer w7: U2.37 5229.1,3529.1 v1(5260,3560) ; J1.6 5279.88,3279.88 v1(5290,3290)
  Bottom Layer w7: v1(5260,3560) 5290,3530 v1(5290,3290)
V33: C3.1 C6.2 C17.1 C18.1 R1.2 R2.2 R3.2 R6.1 U1.13 U2.62 U4.5 U5.1 U6.3 U6.7 U6.8 | length 3248.6
  Top Layer w10: C3.1 5156.97,4104.37 5175.51,4122.91 5189.74,4122.91 U1.13 ; v1(5500,3585) 5527.49,3585 U2.62 5563.28,3549.32 5590.79,3521.81 5605.16,3521.81 5610,3516.97 C6.2
  Top Layer w15: v1(5140,3805) v1(5140,3875) ; C18.1 U6.3
  Top Layer w20: U6.8 U6.7
  Bottom Layer w15: v1(5140,3805) 5140,3743.79 5148.79,3735 5270,3735 5330,3675 5330,3605 5335,3600 ; v1(5140,3875) 5140,4089.8 5155,4104.8 v1(5155,4105) 5155,4225 5200,4270 v1(5530,4270) ; R3.2 R1.2 ; C17.1 5282.66,3062.34 5266.87,3062.34 5242.8,3086.42 U4.5 5242.8,3163.54 5176.97,3229.37 R1.2 ; v1(5466.53,3324.2) 5466.53,3481.53 5520,3535 5520,3564.8 5500,3584.8 v1(5500,3585) 5499.8,3585 5499.42,3584.63 5350.37,3584.63 5335,3600 ; R1.2 R2.2 5145,3580 5165,3600 5335,3600
  Bottom Layer w20: v1(5530,4270) 5580,4220 5580,3851.24 5568.28,3839.53 5565.75,3839.53 5560,3833.78 U5.1
  other v1: 5580,3995
VBAT: C11.2 C15.1 J2.2 Q1.2 U2.3 U3.3 | length 2043.7
  Top Layer w10: U2.3 5563.17,3660.57 5543.38,3640.77 5543.38,3626.62 5567.48,3602.52 5590.88,3602.52 5604.79,3588.62 5630.75,3588.62 C11.2
  Top Layer w15: v1(5405,2875) 5405,2994.63 v1(5410.37,3000)
  Top Layer w20: v1(5585,3080) v1(5638.74,3080)
  Bottom Layer w15: U3.3@5367.5,2872.66 5413.25,2872.66 C15.1 ; Q1.2 5414.27,2995.73 5480.73,2995.73 5529.93,3044.93 5549.73,3044.93 5584.8,3080 v1(5585,3080) ; v1(5415,4345) 5575,4345 5610,4310 5610,3800 5635,3775 v1(5635,3585) 5635,3584.8 5638.74,3581.06 v1(5638.74,3080)
Vref: C4.2 R15.1 R16.1 R17.1 R18.1 R19.1 R20.1 R21.1 R22.1 U2.51 | length 849.9
  Top Layer w5: 5355.63,3115.63 R16.1 ; 5395,3115.63 R18.1 ; 5434.37,3115.63 R20.1 ; R22.1 5473.74,3118.04 5473.81,3117.97
  Top Layer w10: v1(5412.91,3454.1) 5413.3,3454.1 5440.57,3426.83 U2.51 5440.68,3426.94 5420.88,3446.74
  Top Layer w15: R15.1 5355.63,3115.63 R17.1 5395,3115.63 R19.1 5434.37,3115.63 R21.1 5456.4,3117.97 5473.81,3117.97 5491.21,3117.97 5500,3126.76 5500,3236.01 5472.16,3263.85 C4.2@5472.16,3267.16
  Bottom Layer w15: v1(5412.91,3454.1) 5412.91,3453.9 5440,3426.81 5440,3300.2 5467.16,3273.04 v1(5467.16,3272.16)
VSS: C1.2 C2.2 C3.2 C4.1 C5.1 C6.1 C7.2 C8.2 C9.2 C10.2 C11.1 C12.1 C13.1 C14.2 C15.2 C16.2 C17.2 C18.2 J1. J1.1 J1.12 J2. J2.1 J3. J3.1 Q3.2 R7.1 R8.2 R9.2 R12.2 R14.2 SW1.2 U1.18 U1.20 U1.25 U2.16 U2.61 U2.63 U3.2 U4.2 U5.8 U5.9 U5.10 U6.4 X1. | length 6638.3
  Top Layer w7: U1.18 5191.24,4045.67 5213,4045.67 U1.25@5227.32,4060
  Top Layer w10: C3.2@5161.81,4059.2 5176.68,4044.33 5189.74,4044.33 U1.18 ; U1.20 U1.25@5227.32,4060 ; U2.16 5434.3,3821.34 5434.3,3851.07 5433.61,3851.76 5433.61,3858.61 C13.1 ; J1.@5460,2885 5460,2881.14 5481.14,2860 5500.28,2860 5512.87,2872.6 5512.87,2907.13 5505,2915 5505,2915.66 5502.13,2918.54 5502.13,2962.87 5500,2965 ; U2.61 5551.92,3538.19 5522.98,3567.13 5483.73,3567.13 5475,3575.86 5475,3595 5485,3605 5529.76,3605 U2.63 5574.42,3560.46 5594.21,3540.66 5632.63,3540.66 C11.1@5636.97,3545 ; C10.2 5631.39,3618.61 5638.24,3618.61 5638.9,3619.27 5647.19,3619.27 5665,3601.46 v1(5665,3540) C11.1@5643.62,3540 ; C11.1 C11.1@5636.97,3545 ; C6.1 5644.53,3519.84 5644.53,3537.44 C11.1@5636.97,3545 ; C8.2@5650.32,3456.39 C6.1@5650.32,3515
  Top Layer w15: v1(5115,4330) 5115,4261.21 5130,4246.21 ; J1.@5119.45,2885 5119.45,3049.57 5127.15,3057.26 5159.43,3057.26 5163.74,3061.57 J1.1 ; C3.2 5138.79,4065 5130,4073.79 5130,4246.21 ; C1.2 5207.34,4227.34 5207.34,4246.21 5216.13,4255 ; v1(5206.57,2983.91) 5206.57,2923.43 5225,2905 5295,2905 5315,2925 ; C2.2 5275,4245 5265,4255 ; v1(5315,2990) 5315,2925 ; v1(5355,2910) 5330,2910 5315,2925 ; J1.12 5415.71,3061.57 5420.02,3057.26 5452.3,3057.26 5460,3049.57 5460,2975 5470,2965 5500,2965 5555,2965 ; C13.1 5435,3860.34 5457.16,3882.5 C12.1 5460.47,3882.84 5465.1,3887.47 5496.34,3887.47 5563.81,3820 5566,3817.81 5636.71,3817.81 v1(5637.11,3817.41) 5637.11,3822.89 5630,3830 U6.4 5630,4014.22 5655,4039.22 v1(5655,4335) 5581.56,4408.44 5547.85,4408.44 5514.02,4442.28 5514.02,4460 5264.02,4460 5264.02,4442.28 5336.48,4369.82 5356.16,4369.82 5364.41,4361.57 J2.1 5364.41,4330.08 5289.33,4255 5265,4255 ; v1(5495,3300) 5515,3320 ; X1.@5530.2,3424.8 5530.2,3413.13 5518.55,3401.49 5518.55,3384.23 C7.2 5517.16,3379.53 5515,3377.37 5515,3320 ; Q3.2 5583.2,3111.87 5556.87,3111.87 5542.48,3097.48 5542.48,2977.52 5555,2965 ; SW1.2 5593.25,2893.25 5593.25,2917.75 5603.79,2928.29 5612.66,2928.29 R14.2 ; 5590.37,2917.75 5590.37,2953.45 5578.82,2965 5555,2965 ; X1.@5610.93,3435.93 5622.3,3435.93 5639.97,3453.61 5644.22,3453.61 C8.2@5645.88,3451.95 ; C8.2 5648.93,3451.68 5647.82,3450.58 5660,3438.4 5660,3395.62 5602.2,3337.82 5584.38,3320 5515,3320 ; 5130,4246.21 5138.79,4255 5216.13,4255 ; 5216.13,4255 5265,4255
  Bottom Layer w12: 5289,3233.48 5296.48,3226 5296.48,3195.09 J3.1
  Bottom Layer w15: J1.@5119.45,2885 5119.45,2879.78 5131.26,2867.97 5157.66,2867.97 C14.2 R8.2 ; R12.2 5145,2986.97 5124.11,3007.86 5124.11,3044.9 5119.45,3049.57 5125.06,3055.18 5186.42,3055.18 5204.98,3036.62 U4.2 ; v1(5265,3370) 5265,3315.59 5235.95,3286.54 5235.95,3266.87 5267.82,3235 5415,3235 ; C17.2 5286.97,3020.63 5312.66,2994.94 5312.66,2992.34 v1(5315,2990) ; U3.2 5440.57,2909.65 5460,2890.22 J1.@5460,2885 ; v1(5415,3325) 5415,3235 ; J1.@5460,3049.57 5462.66,3052.22 5462.66,3124.63 5467.34,3129.31 5509.31,3129.31 5520,3140 J3.@5520,3252.5 ; v1(5637.11,3817.41) 5652.59,3817.41 5665,3805 v1(5665,3540) ; 5415,3235 5502.5,3235 J3.@5520,3252.5 ; J3.@5520,3252.5 5534.37,3266.87 5534.37,3286.34 5520,3271.97 J3.@5520,3252.5
  Bottom Layer w20: v1(5115,4330) 5115,3860 5135.47,3839.53 5204.25,3839.53 5210,3833.78 U5.8
X32I: C9.1 R5.1 U2.5 X2.2 | length 169
  Top Layer w7: U2.5 5540.9,3683.72 5566.52,3709.34 5566.52,3739.56 X2.2 5573.48,3753.48 C9.1 5630,3770 R5.1
X32O: C10.1 R5.2 U2.4 X2.1 | length 208.1
  Top Layer w7: U2.4 5552.03,3672.03 5575,3695 5588.19,3695 5605.35,3677.84 X2.1@5635,3677.84 ; C10.1 5635,3670.68 X2.1@5635,3677.84 ; R5.2 5657.84,3730.73 5635,3707.89 X2.1 X2.1@5635,3677.84
pads on no net: J1.3 J1.9 J1.10 J3.2 SW1.1@5630.28,2885 U1.1 U1.2 U1.3 U1.4 U1.5 U1.6 U1.7 U1.14 U1.15 U1.16 U1.17 U1.19 U1.21 U2.2 U2.6 U2.7 U2.8 U2.31 U2.32 U2.33 U2.34 U2.35 U2.36 U2.54 U2.55 U2.56 U2.64 U4.4

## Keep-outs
Keep-Out Layer:
  the board outline again, w10

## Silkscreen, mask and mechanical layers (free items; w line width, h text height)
Top Overlay:
  drawing of 740 lines, arcs and shapes, not listed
